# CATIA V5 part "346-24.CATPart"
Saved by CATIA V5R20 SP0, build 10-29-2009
Part number: 346-24
Definition: NONE
Nomenclature: 346-24
Source: Unknown
Description: 346-24
Bounding box of the stored display mesh (mm): x 0 to 63, y -31.5 to 31.5, z -31.5 to 31.5
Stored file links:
  C:\Users\Utente\Desktop\IO LAVORO\3D X SITO CF\X SITO\3D files 346\346-24.CATPart
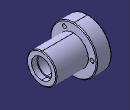
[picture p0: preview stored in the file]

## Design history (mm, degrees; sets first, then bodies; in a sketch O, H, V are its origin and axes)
Body1 "346-24" (main body)
  Solid1: solid without history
